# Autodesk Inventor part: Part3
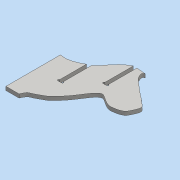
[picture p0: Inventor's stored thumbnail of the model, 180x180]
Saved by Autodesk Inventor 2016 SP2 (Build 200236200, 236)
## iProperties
Created: 2017-07
Part Number: Part3
Material: Generic
Document SubType Name: Modeling
Designer: Mohamed A.
Density: 1 g/cm^3
Appearance: Default
Author: Mohamed A.
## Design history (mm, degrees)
sketch "Sketch1"
  geometry: L1 (-0.177, 221.144)-(394.816, 221.144); L2 (394.816, 221.144)-(394.816, -337.581); L3 (394.816, -337.581)-(-0.177, -337.581); L4 (-0.177, -337.581)-(-0.177, 221.144); L5 (29.162, -1.845)-(-10.139, -1.845); L6 (11.861, -1.845)-(29.162, -1.845); L7 (53.147, 176.701)-(53.147, 96.453); L8 (53.147, 90.453)-(64.147, 90.453); L9 (64.147, 90.453)-(64.147, 96.453); L10 (139.111, 242.269)-(139.111, 157.269); L11 (139.111, 151.269)-(128.111, 151.269); L12 (128.111, 151.269)-(128.111, 157.269); L13 (-10.139, -1.845)-(-10.139, 161.584); L14 (-10.139, 161.584)-(-1.396, 161.925); L15 (-1.396, 161.925)-(3.672, 157.595); L16 (3.672, 157.595)-(20.856, 161.665); L17 (20.856, 161.665)-(41.287, 169.174); L18 (41.287, 169.174)-(53.147, 176.701); L19 (64.147, 181.896)-(78.883, 188.133); L20 (78.883, 188.133)-(92.368, 223.33); L21 (92.368, 223.33)-(116.498, 235.805); L22 (116.498, 235.805)-(128.111, 242.416); L23 (139.111, 242.269)-(166.121, 239.967); L24 (166.121, 239.967)-(166.174, 239.967); L25 (166.174, 239.967)-(155.742, 237.58); L26 (155.742, 237.58)-(162.026, 227.554); L27 (162.026, 227.554)-(164.858, 221.283); L28 (164.858, 221.283)-(169.114, 215.7); L29 (169.114, 215.7)-(213.096, 177.544); L30 (213.096, 177.544)-(219.565, 173.113); L31 (219.565, 173.113)-(227.789, 167.48); L32 (227.789, 167.48)-(230.731, 162.619); L33 (230.731, 162.619)-(237.78, 158.878); L34 (237.78, 158.878)-(247.992, 150.817); L35 (247.992, 150.817)-(250.49, 143.704); L36 (250.49, 143.704)-(237.364, 115.797); L37 (237.364, 115.797)-(234.093, 112.438); L38 (234.093, 112.438)-(230.706, 109.856); L39 (230.706, 109.856)-(219.066, 105.578); L40 (219.066, 105.578)-(217.797, 105.112); L41 (217.797, 105.112)-(200.323, 102.3); L42 (200.323, 102.3)-(197.368, 102.3); L43 (197.368, 102.3)-(184.069, 105.803); L44 (184.069, 105.803)-(173.119, 113.533); L45 (173.119, 113.533)-(160.866, 121.591); L46 (160.866, 121.591)-(154.202, 124.37); L47 (154.202, 124.37)-(146.54, 120.401); L48 (146.54, 120.401)-(137.444, 111.056); L49 (137.444, 111.056)-(129.557, 98.748); L50 (129.557, 98.748)-(118.922, 82.675); L51 (118.922, 82.675)-(109.003, 67.199); L52 (109.003, 67.199)-(84.085, 39.014); L53 (84.085, 39.014)-(75.361, 33.279); L54 (75.361, 33.279)-(73.093, 32.445); L55 (73.093, 32.445)-(51.773, 20.112); L56 (51.773, 20.112)-(43.981, 17.248); L57 (43.981, 17.248)-(38.649, 15.288); L58 (38.649, 15.288)-(34.538, 9.392); L59 (34.538, 9.392)-(31.533, 3.653); L60 (31.533, 3.653)-(29.162, -1.845); L61 (128.111, 157.269)-(128.111, 242.416); L62 (139.111, 157.269)-(139.111, 151.269); L63 (53.147, 96.453)-(53.147, 90.453); L64 (64.147, 96.453)-(64.147, 181.896); A1 r 3 centre (128.111, 154.269) between (128.111, 157.269) and (128.111, 151.269); A2 r 3 centre (139.111, 154.269) between (139.111, 157.269) and (139.111, 151.269); A3 r 3 centre (128.111, 154.269) between (128.111, 151.269) and (128.111, 157.269); A4 r 3 centre (139.111, 154.269) between (139.111, 151.269) and (139.111, 157.269); A5 r 3 centre (53.147, 93.453) between (53.147, 90.453) and (53.147, 96.453); A6 r 3 centre (64.147, 93.453) between (64.147, 90.453) and (64.147, 96.453); A7 r 3 centre (64.147, 93.453) between (64.147, 96.453) and (64.147, 90.453); A8 r 3 centre (53.147, 93.453) between (53.147, 96.453) and (53.147, 90.453); 2 further points; 1 other entity
  constraints: 26 end point, 16 point on circle, 8 centre point, 6 perpendicular, 5 parallel, 5 vertical, 4 midpoint, 3 point on line, 1 collinear, 1 horizontal, 22 other
  dimensions: "d42" = 11 distance of L8.start L8.end; "d43" = 11 distance of L11.start L11.end; "d63" = 91 vertical distance of L11.end L10.start; "d115" = 6 diameter of A1; "d116" = 6 diameter of A2; "d119" = 6 diameter of A5; "d120" = 6 diameter of A6
extrude "Extrusion1" new body sketch "Sketch1" distance "d61" = 11; taper "d62" = 0 deg
body "Solid1"
node "Image2"
